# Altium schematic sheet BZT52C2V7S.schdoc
size 127 x 101 mm
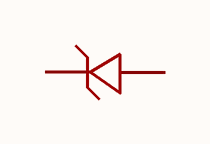
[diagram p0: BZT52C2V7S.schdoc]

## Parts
ZD?  bzt52c2v7s_c22607  [SOD-323_L1.8-W1.3-LS2.5-RD]  (value not drawn)

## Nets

Not connected (* = marked no-connect by the designer): ZD? 1(K) 2(A)

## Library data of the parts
ZD? = bzt52c2v7s_c22607: 二极管配置:1个独立式;稳压值(标称值):2.7V;稳压值(范围值):2.5V~2.9V;耗散功率(Pd):200mW;; Manufacturer: CJ(江苏长电/长晶); AddInBom: yes; ModelId: db63db13d9e342eb939127d413d6200b; ModelTransform: 104.3305,51.181,0,0,0,0,0,-0.004,0; Diode Configuration: 1个独立式; Zener Voltage(Nom): 2.7V; Reverse Leakage Current (Ir): 20uA@1V; Pd - Power Dissipation: 200mW; Impedance(Zzt): 100Ω; Impedance(Zzk): 600Ω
